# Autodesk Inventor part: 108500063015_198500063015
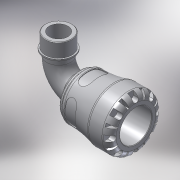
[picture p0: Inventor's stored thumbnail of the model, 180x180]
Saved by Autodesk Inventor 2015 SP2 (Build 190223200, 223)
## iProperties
Created: 2016-12
Part Number: 108500063015_198500063015
Material: PVC-Piping
Description: PLASSON 90° ELBOW WITH THREADED MALE OFFTAKE 63X1.1/2" SERIES 1
Document SubType Name: Modeling
Designer: KIM
Mass: 691.796 g
Surface Area: 886.276 cm^2
Volume: 494.14 cm^3
Density: 1.4 g/cm^3
Appearance: Smooth - White
Author: KIM
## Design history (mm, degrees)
derived "1085.ipt"
feature "Solid1::1085.ipt"
tag "TaggingFeature1"
body "Solid1"
other parameters: "d1" = 37.8, "d2" = 63, "d3" = 78.75, "d4" = 103, "d8" = 87.55, "d13" = 9.7, "d14" = 9.7, "d15" = 0, "d17" = 360 deg, "d19" = 8 deg, "d20" = 1.26, "d21" = 1.26, "d22" = 8 deg, "d24" = 0, "d26" = 360 deg, "d33" = 10.3, "d43" = 80.34, "d51" = 1.03, "d54" = 22.05, "d55" = 13.86, "d57" = 19.012, "d58" = 0, "d74" = 0, "d82" = 1.26, "d115" = 360 deg, "d207" = 90 deg, "d228" = 18.7425, "d247" = 2.06, "d248" = 5.4, "d268" = 48.1525, "d269" = 5.4, "d270" = 143, "d276" = 47.803, "d277" = 21, "d278" = 52.5833, "d279" = 78, "d280" = 23.1, "d281" = 7.17045, "d283" = 43.0227, "d286" = 0, "d287" = 0, "d288" = 33.4621, "d290" = 18.65865, "d292" = 30 deg, "d_" = 63, "E_" = 103, "A_" = 143, "A_1" = 78, "l_2" = 21, "R_" = 47.803, "d9" = 12.125, "d11" = 103, "d12" = 78.75, "d289" = 33.4621
